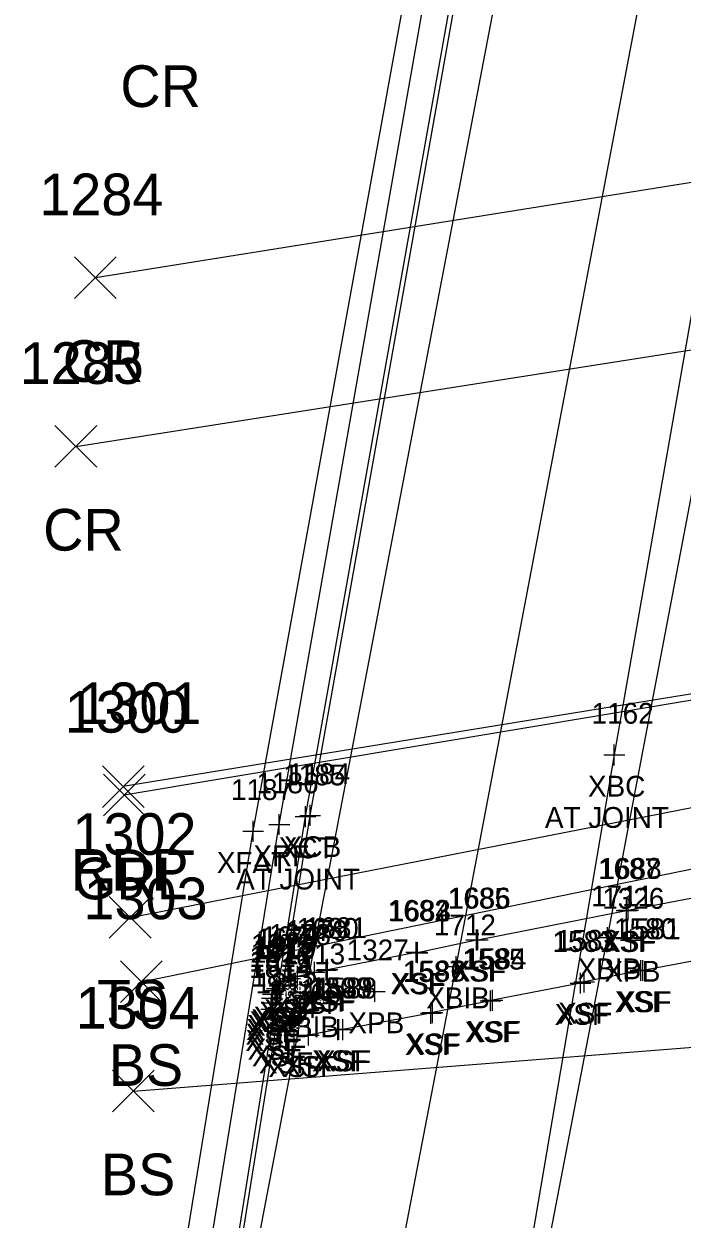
# Model space of a CAD drawing. Extents: x 1683147 to 1683637, y 416837 to 418211.
# Drawn here: x 1683200 to 1683231.5, y 417486.5 to 417543.9 of the extents above; entities that cross this region are included whole.
import ezdxf

# ---------------------------------------------------------------- set-up
doc = ezdxf.new("R2010")
doc.units = 0
for name, color, linetype in [('B_A', 7, 'Continuous'), ('B_C', 7, 'Continuous'), ('B_I', 7, 'Continuous'), ('B_TIC', 7, 'Continuous'), ('BB', 7, 'Continuous'), ('BDC', 7, 'Continuous'), ('BDEFAULT', 7, 'Continuous'), ('BELB', 7, 'Continuous'), ('BF', 7, 'Continuous'), ('BR', 7, 'Continuous'), ('L_A', 7, 'Continuous'), ('L_I', 7, 'Continuous'), ('L_TIC', 7, 'Continuous'), ('LELB', 7, 'Continuous'), ('P_A', 7, 'Continuous'), ('P_I', 7, 'Continuous'), ('P_TIC', 7, 'Continuous'), ('PET', 7, 'Continuous'), ('PRC', 7, 'Continuous'), ('R_A', 7, 'Continuous'), ('R_I', 7, 'Continuous'), ('R_TIC', 7, 'Continuous'), ('RGR', 7, 'Continuous')]:
    doc.layers.add(name, color=color, linetype=linetype)

msp = doc.modelspace()

# ---------------------------------------------------------------- linework, layer by layer
at = {"layer": 'B_TIC'}
for p, q in [((1683228.277, 417508.761), (1683228.353, 417508.761)), ((1683213.466, 417505.801), (1683213.541, 417505.801)), ((1683213.696, 417505.86), (1683213.771, 417505.86)), ((1683210.961, 417505.098), (1683211.036, 417505.098)), ((1683212.21, 417505.421), (1683212.286, 417505.421)), ((1683228.867, 417501.303), (1683228.943, 417501.303)), ((1683228.94, 417501.313), (1683229.016, 417501.313)), ((1683221.664, 417499.883), (1683221.739, 417499.883)), ((1683221.732, 417499.891), (1683221.808, 417499.891)), ((1683227.945, 417499.995), (1683228.021, 417499.995)), ((1683229.073, 417499.878), (1683229.149, 417499.878)), ((1683218.784, 417499.298), (1683218.859, 417499.298)), ((1683218.837, 417499.271), (1683218.913, 417499.271)), ((1683218.841, 417499.282), (1683218.916, 417499.282)), ((1683213.088, 417498.141), (1683213.163, 417498.141)), ((1683213.903, 417498.334), (1683213.978, 417498.334)), ((1683214.456, 417498.436), (1683214.532, 417498.436)), ((1683214.526, 417498.468), (1683214.602, 417498.468)), ((1683220.688, 417498.601), (1683220.763, 417498.601)), ((1683229.543, 417498.415), (1683229.618, 417498.415)), ((1683229.653, 417498.419), (1683229.728, 417498.419)), ((1683212.098, 417497.554), (1683212.173, 417497.554)), ((1683212.098, 417497.554), (1683212.173, 417497.554)), ((1683212.224, 417497.673), (1683212.299, 417497.673)), ((1683212.224, 417497.673), (1683212.299, 417497.673)), ((1683212.498, 417497.926), (1683212.573, 417497.926)), ((1683212.726, 417498.034), (1683212.801, 417498.034)), ((1683226.658, 417497.807), (1683226.734, 417497.807)), ((1683226.83, 417497.866), (1683226.906, 417497.866)), ((1683211.866, 417497.087), (1683211.941, 417497.087)), ((1683211.908, 417497.284), (1683211.983, 417497.284)), ((1683212.021, 417497.459), (1683212.097, 417497.459)), ((1683213.457, 417497.213), (1683213.532, 417497.213)), ((1683216.79, 417497.404), (1683216.865, 417497.404)), ((1683222.343, 417496.96), (1683222.419, 417496.96)), ((1683222.438, 417496.984), (1683222.514, 417496.984)), ((1683211.829, 417496.558), (1683211.905, 417496.558)), ((1683211.836, 417496.859), (1683211.912, 417496.859)), ((1683219.48, 417496.362), (1683219.555, 417496.362)), ((1683219.557, 417496.393), (1683219.632, 417496.393)), ((1683211.935, 417496.137), (1683212.01, 417496.137)), ((1683212.138, 417495.814), (1683212.214, 417495.814)), ((1683212.476, 417495.481), (1683212.552, 417495.481)), ((1683212.932, 417495.301), (1683213.007, 417495.301)), ((1683213.62, 417495.308), (1683213.695, 417495.308)), ((1683215.027, 417495.578), (1683215.102, 417495.578)), ((1683215.072, 417495.58), (1683215.147, 417495.58)), ((1683215.072, 417495.58), (1683215.147, 417495.58)), ((1683215.257, 417495.576), (1683215.333, 417495.576))]:
    msp.add_line(p, q, dxfattribs=at)
for points in [[(1683228.274, 417508.261), (1683228.274, 417509.261)], [(1683227.774, 417508.761), (1683228.774, 417508.761)], [(1683213.462, 417505.301), (1683213.462, 417506.301)], [(1683213.692, 417505.36), (1683213.692, 417506.36)], [(1683210.957, 417504.598), (1683210.957, 417505.598)], [(1683212.207, 417504.921), (1683212.207, 417505.921)], [(1683212.962, 417505.801), (1683213.962, 417505.801)], [(1683213.192, 417505.86), (1683214.192, 417505.86)], [(1683210.457, 417505.098), (1683211.457, 417505.098)], [(1683211.707, 417505.421), (1683212.707, 417505.421)], [(1683228.864, 417500.803), (1683228.864, 417501.803)], [(1683228.937, 417500.813), (1683228.937, 417501.813)], [(1683228.364, 417501.303), (1683229.364, 417501.303)], [(1683228.437, 417501.313), (1683229.437, 417501.313)], [(1683221.66, 417499.383), (1683221.66, 417500.383)], [(1683221.729, 417499.391), (1683221.729, 417500.391)], [(1683227.942, 417499.495), (1683227.942, 417500.495)], [(1683229.07, 417499.378), (1683229.07, 417500.378)], [(1683218.78, 417498.798), (1683218.78, 417499.798)], [(1683218.837, 417498.782), (1683218.837, 417499.782)], [(1683221.16, 417499.883), (1683222.16, 417499.883)], [(1683221.229, 417499.891), (1683222.229, 417499.891)], [(1683227.442, 417499.995), (1683228.442, 417499.995)], [(1683228.57, 417499.878), (1683229.57, 417499.878)], [(1683218.28, 417499.298), (1683219.28, 417499.298)], [(1683218.334, 417499.271), (1683219.334, 417499.271)], [(1683218.337, 417499.282), (1683219.337, 417499.282)], [(1683218.834, 417498.771), (1683218.834, 417499.771)], [(1683213.084, 417497.641), (1683213.084, 417498.641)], [(1683213.899, 417497.834), (1683213.899, 417498.834)], [(1683214.453, 417497.936), (1683214.453, 417498.936)], [(1683214.523, 417497.968), (1683214.523, 417498.968)], [(1683220.685, 417498.101), (1683220.685, 417499.101)], [(1683229.539, 417497.915), (1683229.539, 417498.915)], [(1683229.649, 417497.919), (1683229.649, 417498.919)], [(1683212.094, 417497.054), (1683212.094, 417498.054)], [(1683212.094, 417497.054), (1683212.094, 417498.054)], [(1683212.22, 417497.173), (1683212.22, 417498.173)], [(1683212.22, 417497.173), (1683212.22, 417498.173)], [(1683212.494, 417497.426), (1683212.494, 417498.426)], [(1683212.584, 417498.141), (1683213.584, 417498.141)], [(1683212.723, 417497.534), (1683212.723, 417498.534)], [(1683213.399, 417498.334), (1683214.399, 417498.334)], [(1683213.953, 417498.436), (1683214.953, 417498.436)], [(1683214.023, 417498.468), (1683215.023, 417498.468)], [(1683220.185, 417498.601), (1683221.185, 417498.601)], [(1683226.655, 417497.307), (1683226.655, 417498.307)], [(1683226.827, 417497.366), (1683226.827, 417498.366)], [(1683229.039, 417498.415), (1683230.039, 417498.415)], [(1683229.149, 417498.419), (1683230.149, 417498.419)], [(1683211.594, 417497.554), (1683212.594, 417497.554)], [(1683211.594, 417497.554), (1683212.594, 417497.554)], [(1683211.72, 417497.673), (1683212.72, 417497.673)], [(1683211.72, 417497.673), (1683212.72, 417497.673)], [(1683211.862, 417496.587), (1683211.862, 417497.587)], [(1683211.904, 417496.784), (1683211.904, 417497.784)], [(1683211.994, 417497.926), (1683212.994, 417497.926)], [(1683212.018, 417496.959), (1683212.018, 417497.959)], [(1683212.223, 417498.034), (1683213.223, 417498.034)], [(1683213.453, 417496.713), (1683213.453, 417497.713)], [(1683216.786, 417496.904), (1683216.786, 417497.904)], [(1683222.435, 417496.484), (1683222.435, 417497.484)], [(1683226.155, 417497.807), (1683227.155, 417497.807)], [(1683226.327, 417497.866), (1683227.327, 417497.866)], [(1683211.362, 417497.087), (1683212.362, 417497.087)], [(1683211.404, 417497.284), (1683212.404, 417497.284)], [(1683211.518, 417497.459), (1683212.518, 417497.459)], [(1683211.826, 417496.058), (1683211.826, 417497.058)], [(1683211.833, 417496.359), (1683211.833, 417497.359)], [(1683212.953, 417497.213), (1683213.953, 417497.213)], [(1683216.286, 417497.404), (1683217.286, 417497.404)], [(1683221.84, 417496.96), (1683222.84, 417496.96)], [(1683221.935, 417496.984), (1683222.935, 417496.984)], [(1683222.34, 417496.46), (1683222.34, 417497.46)], [(1683211.326, 417496.558), (1683212.326, 417496.558)], [(1683211.333, 417496.859), (1683212.333, 417496.859)], [(1683211.931, 417495.637), (1683211.931, 417496.637)], [(1683218.976, 417496.362), (1683219.976, 417496.362)], [(1683219.054, 417496.393), (1683220.054, 417496.393)], [(1683219.476, 417495.862), (1683219.476, 417496.862)], [(1683219.554, 417495.893), (1683219.554, 417496.893)], [(1683211.431, 417496.137), (1683212.431, 417496.137)], [(1683211.635, 417495.814), (1683212.635, 417495.814)], [(1683212.135, 417495.314), (1683212.135, 417496.314)], [(1683212.473, 417494.981), (1683212.473, 417495.981)], [(1683212.928, 417494.801), (1683212.928, 417495.801)], [(1683213.616, 417494.808), (1683213.616, 417495.808)], [(1683215.023, 417495.078), (1683215.023, 417496.078)], [(1683215.069, 417495.08), (1683215.069, 417496.08)], [(1683215.069, 417495.08), (1683215.069, 417496.08)], [(1683215.254, 417495.076), (1683215.254, 417496.076)], [(1683211.973, 417495.481), (1683212.973, 417495.481)], [(1683212.428, 417495.301), (1683213.428, 417495.301)], [(1683213.116, 417495.308), (1683214.116, 417495.308)], [(1683214.523, 417495.578), (1683215.523, 417495.578)], [(1683214.569, 417495.58), (1683215.569, 417495.58)], [(1683214.569, 417495.58), (1683215.569, 417495.58)], [(1683214.754, 417495.576), (1683215.754, 417495.576)]]:
    msp.add_lwpolyline(points, dxfattribs=at)
at = {"layer": 'BB'}
for points in [[(1683218.639, 417451.571), (1683227.942, 417499.995), (1683246.282, 417596.559), (1683255.565, 417645.821)], [(1683211.398, 417450.232), (1683220.685, 417498.601), (1683239.091, 417595.537), (1683248.339, 417644.482)], [(1683204.248, 417448.864), (1683213.453, 417497.213), (1683232.034, 417594.621), (1683241.123, 417643.096)]]:
    msp.add_lwpolyline(points, dxfattribs=at)
at = {"layer": 'BDC'}
for points in [[(1683204.26, 417446.59), (1683207.746, 417469.989), (1683213.462, 417505.801), (1683221.311, 417549.93), (1683228.046, 417584.722), (1683234.074, 417613.621), (1683241.065, 417645.18)], [(1683204.523, 417446.635), (1683207.943, 417470.136), (1683213.692, 417505.86), (1683221.542, 417549.946), (1683228.342, 417584.807), (1683234.248, 417613.515), (1683241.392, 417644.923)]]:
    msp.add_lwpolyline(points, dxfattribs=at)
at = {"layer": 'BDEFAULT'}
for points in [[(1683212.22, 417497.673), (1683212.494, 417497.926), (1683212.723, 417498.034), (1683213.084, 417498.141), (1683213.899, 417498.334), (1683214.453, 417498.436), (1683214.523, 417498.468), (1683218.78, 417499.298), (1683218.834, 417499.271), (1683218.837, 417499.282), (1683221.66, 417499.883), (1683221.729, 417499.891), (1683228.864, 417501.303), (1683228.937, 417501.313), (1683233.187, 417502.135)], [(1683233.899, 417499.221), (1683229.649, 417498.419), (1683229.539, 417498.415), (1683226.827, 417497.866), (1683226.655, 417497.807), (1683222.435, 417496.984), (1683222.34, 417496.96), (1683219.554, 417496.393), (1683219.476, 417496.362), (1683215.254, 417495.576), (1683215.069, 417495.58)], [(1683215.069, 417495.58), (1683215.023, 417495.578), (1683213.616, 417495.308), (1683212.928, 417495.301), (1683212.473, 417495.481), (1683212.135, 417495.814), (1683211.931, 417496.137), (1683211.826, 417496.558), (1683211.833, 417496.859), (1683211.862, 417497.087), (1683211.904, 417497.284), (1683212.018, 417497.459), (1683212.094, 417497.554)], [(1683212.22, 417497.673), (1683212.094, 417497.554)]]:
    msp.add_lwpolyline(points, dxfattribs=at)
at = {"layer": 'BELB'}
msp.add_lwpolyline([(1683255.821, 417648.166), (1683248.035, 417613.702), (1683243.06, 417587.805), (1683234.781, 417546.02), (1683228.274, 417508.761), (1683222.317, 417473.758), (1683218.863, 417449.537)], dxfattribs=at)
at = {"layer": 'BF'}
msp.add_lwpolyline([(1683201.852, 417446.968), (1683205.241, 417469.957), (1683210.957, 417505.098), (1683219.149, 417550.319), (1683225.494, 417584.011), (1683231.655, 417613.999), (1683238.79, 417645.736)], dxfattribs=at)
at = {"layer": 'BR'}
msp.add_lwpolyline([(1683201.249, 417434.944), (1683203.019, 417446.95), (1683206.413, 417469.882), (1683212.207, 417505.421), (1683220.042, 417550.002), (1683226.73, 417584.319), (1683232.917, 417613.974), (1683239.772, 417645.191), (1683242.155, 417655.448)], dxfattribs=at)
at = {"layer": 'L_TIC'}
for points in [[(1683204.058, 417499.966), (1683206.058, 417501.966)], [(1683206.058, 417499.966), (1683204.058, 417501.966)], [(1683204.591, 417496.875), (1683206.591, 417498.875)], [(1683206.591, 417496.875), (1683204.591, 417498.875)], [(1683204.213, 417491.626), (1683206.213, 417493.626)], [(1683206.213, 417491.626), (1683204.213, 417493.626)]]:
    msp.add_lwpolyline(points, dxfattribs=at)
at = {"layer": 'LELB'}
for points in [[(1683205.058, 417500.966), (1683236.725, 417507.171), (1683266.627, 417512.319), (1683295.742, 417517.653), (1683322.975, 417523.071), (1683351.626, 417530.069)], [(1683205.591, 417497.875), (1683237.075, 417504.337), (1683268.914, 417505.721), (1683296.171, 417510.545), (1683323.546, 417516.347), (1683350.433, 417523.399)], [(1683205.213, 417492.626), (1683239.174, 417495.288), (1683270.177, 417500.965), (1683298.559, 417502.586), (1683327.653, 417507.076), (1683349.696, 417514.294)]]:
    msp.add_lwpolyline(points, dxfattribs=at)
at = {"layer": 'P_TIC'}
for points in [[(1683202.393, 417530.667), (1683204.393, 417532.667)], [(1683204.393, 417530.667), (1683202.393, 417532.667)], [(1683201.452, 417522.569), (1683203.452, 417524.569)], [(1683203.452, 417522.569), (1683201.452, 417524.569)], [(1683203.728, 417506.24), (1683205.728, 417508.24)], [(1683205.728, 417506.24), (1683203.728, 417508.24)]]:
    msp.add_lwpolyline(points, dxfattribs=at)
at = {"layer": 'PET'}
msp.add_lwpolyline([(1683351.521, 417537.139), (1683327.502, 417531.164), (1683310.333, 417527.312), (1683275.263, 417519.769), (1683242.13, 417513.342), (1683204.728, 417507.24)], dxfattribs=at)
at = {"layer": 'PRC'}
for points in [[(1683342.592, 417562.589), (1683311.955, 417553.502), (1683276.156, 417545.385), (1683245.179, 417538.35), (1683203.393, 417531.667)], [(1683202.452, 417523.569), (1683242.343, 417529.845), (1683281.666, 417537.682), (1683320.124, 417546.282), (1683360.503, 417556.965)]]:
    msp.add_lwpolyline(points, dxfattribs=at)
at = {"layer": 'R_TIC'}
for points in [[(1683203.773, 417505.832), (1683205.773, 417507.832)], [(1683205.773, 417505.832), (1683203.773, 417507.832)]]:
    msp.add_lwpolyline(points, dxfattribs=at)
at = {"layer": 'RGR'}
msp.add_lwpolyline([(1683351.634, 417536.475), (1683327.504, 417530.568), (1683310.27, 417526.858), (1683275.284, 417519.336), (1683242.138, 417513.085), (1683204.773, 417506.832)], dxfattribs=at)

# ---------------------------------------------------------------- texts
at = {"layer": 'B_A'}
for s, p in [('XBC', (1683227.01, 417506.761)), ('XRF', (1683210.967, 417503.421)), ('XCT', (1683212.183, 417503.801)), ('XCB', (1683212.428, 417503.86)), ('XFAT', (1683209.213, 417503.098)), ('XSF', (1683227.624, 417499.303)), ('XSF', (1683227.697, 417499.313)), ('XSF', (1683220.42, 417497.883)), ('XSF', (1683220.489, 417497.891)), ('XBIB', (1683226.513, 417497.995)), ('XPB', (1683227.806, 417497.878)), ('XSF', (1683217.54, 417497.298)), ('XSF', (1683217.594, 417497.271)), ('XSF', (1683217.597, 417497.282)), ('XSF', (1683213.283, 417496.468)), ('XBIB', (1683219.255, 417496.601)), ('XSF', (1683211.254, 417495.926)), ('XSF', (1683211.482, 417496.034)), ('XSF', (1683211.844, 417496.141)), ('XSF', (1683212.659, 417496.334)), ('XSF', (1683213.213, 417496.436)), ('XSF', (1683228.299, 417496.415)), ('XSF', (1683228.409, 417496.419)), ('XSF', (1683210.778, 417495.459)), ('XSF', (1683210.854, 417495.554)), ('XSF', (1683210.854, 417495.554)), ('XSF', (1683210.98, 417495.673)), ('XSF', (1683210.98, 417495.673)), ('XPB', (1683215.522, 417495.404)), ('XSF', (1683225.415, 417495.807)), ('XSF', (1683225.586, 417495.866)), ('XSF', (1683210.593, 417494.859)), ('XSF', (1683210.622, 417495.087)), ('XSF', (1683210.664, 417495.284)), ('XBIB', (1683212.024, 417495.213)), ('XSF', (1683221.099, 417494.96)), ('XSF', (1683221.195, 417494.984)), ('XSF', (1683210.586, 417494.558)), ('XSF', (1683218.236, 417494.362)), ('XSF', (1683218.313, 417494.393)), ('XSF', (1683210.691, 417494.137)), ('XSF', (1683210.895, 417493.814)), ('XSF', (1683211.233, 417493.481)), ('XSF', (1683211.688, 417493.301)), ('XSF', (1683212.376, 417493.308)), ('XSF', (1683213.783, 417493.578)), ('XSF', (1683213.828, 417493.58)), ('XSF', (1683213.828, 417493.58)), ('XSF', (1683214.014, 417493.576))]:
    msp.add_text(s, height=1, dxfattribs=at).set_placement(p)
at = {"layer": 'B_C'}
for p in [(1683224.947, 417505.261), (1683210.135, 417502.301)]:
    msp.add_text('AT JOINT', height=1, dxfattribs=at).set_placement(p)
at = {"layer": 'B_I'}
for s, p in [('1162', (1683227.187, 417510.261)), ('1186', (1683211.116, 417506.921)), ('1185', (1683212.399, 417507.301)), ('1184', (1683212.629, 417507.36)), ('1187', (1683209.894, 417506.598)), ('1687', (1683227.494, 417502.803)), ('1688', (1683227.567, 417502.813)), ('1685', (1683220.29, 417501.383)), ('1686', (1683220.331, 417501.391)), ('1711', (1683227.162, 417501.495)), ('1326', (1683227.696, 417501.378)), ('1682', (1683217.41, 417500.798)), ('1683', (1683217.464, 417500.771)), ('1684', (1683217.467, 417500.782)), ('1680', (1683213.04, 417499.936)), ('1681', (1683213.436, 417499.968)), ('1712', (1683219.622, 417500.101)), ('1580', (1683228.26, 417499.919)), ('1581', (1683228.476, 417499.915)), ('1676', (1683211.097, 417499.426)), ('1677', (1683211.353, 417499.534)), ('1678', (1683211.714, 417499.641)), ('1679', (1683212.525, 417499.834)), ('1582', (1683225.48, 417499.366)), ('1817', (1683210.842, 417498.784)), ('1675', (1683210.85, 417499.173)), ('1675', (1683210.85, 417499.173)), ('1818', (1683210.955, 417498.959)), ('1819', (1683211.028, 417499.054)), ('1819', (1683211.028, 417499.054)), ('1327', (1683215.44, 417498.904)), ('1583', (1683225.309, 417499.307)), ('1815', (1683210.77, 417498.359)), ('1816', (1683210.772, 417498.587)), ('1713', (1683212.391, 417498.713)), ('1585', (1683220.993, 417498.46)), ('1584', (1683221.088, 417498.484)), ('1814', (1683210.763, 417498.058)), ('1813', (1683210.868, 417497.637)), ('1587', (1683218.13, 417497.862)), ('1586', (1683218.18, 417497.893)), ('1812', (1683211.072, 417497.314)), ('1808', (1683213.637, 417497.078)), ('1589', (1683213.718, 417497.08)), ('1589', (1683213.718, 417497.08)), ('1588', (1683213.908, 417497.076)), ('1811', (1683211.693, 417496.981)), ('1810', (1683211.822, 417496.801)), ('1809', (1683212.226, 417496.808))]:
    msp.add_text(s, height=1, dxfattribs=at).set_placement(p)
at = {"layer": 'L_A'}
for s, p in [('TS', (1683203.467, 417495.966)), ('BS', (1683204.032, 417492.875)), ('BS', (1683203.654, 417487.626))]:
    msp.add_text(s, height=2, dxfattribs=at).set_placement(p)
at = {"layer": 'L_I'}
for s, p in [('1302', (1683202.286, 417503.966)), ('1303', (1683202.819, 417500.875)), ('1304', (1683202.442, 417495.626))]:
    msp.add_text(s, height=2, dxfattribs=at).set_placement(p)
at = {"layer": 'P_A'}
for s, p in [('CR', (1683204.587, 417539.862)), ('CR', (1683201.826, 417526.667)), ('CR', (1683200.885, 417518.569)), ('RDP', (1683202.216, 417502.24))]:
    msp.add_text(s, height=2, dxfattribs=at).set_placement(p)
at = {"layer": 'P_I'}
for s, p in [('1284', (1683200.7, 417534.667)), ('1285', (1683199.759, 417526.569)), ('1301', (1683202.523, 417510.24))]:
    msp.add_text(s, height=2, dxfattribs=at).set_placement(p)
at = {"layer": 'R_A'}
msp.add_text('GRL', height=2, dxfattribs=at).set_placement((1683202.316, 417501.832))
at = {"layer": 'R_I'}
msp.add_text('1300', height=2, dxfattribs=at).set_placement((1683201.914, 417509.832))

doc.saveas('drawing.dxf')
